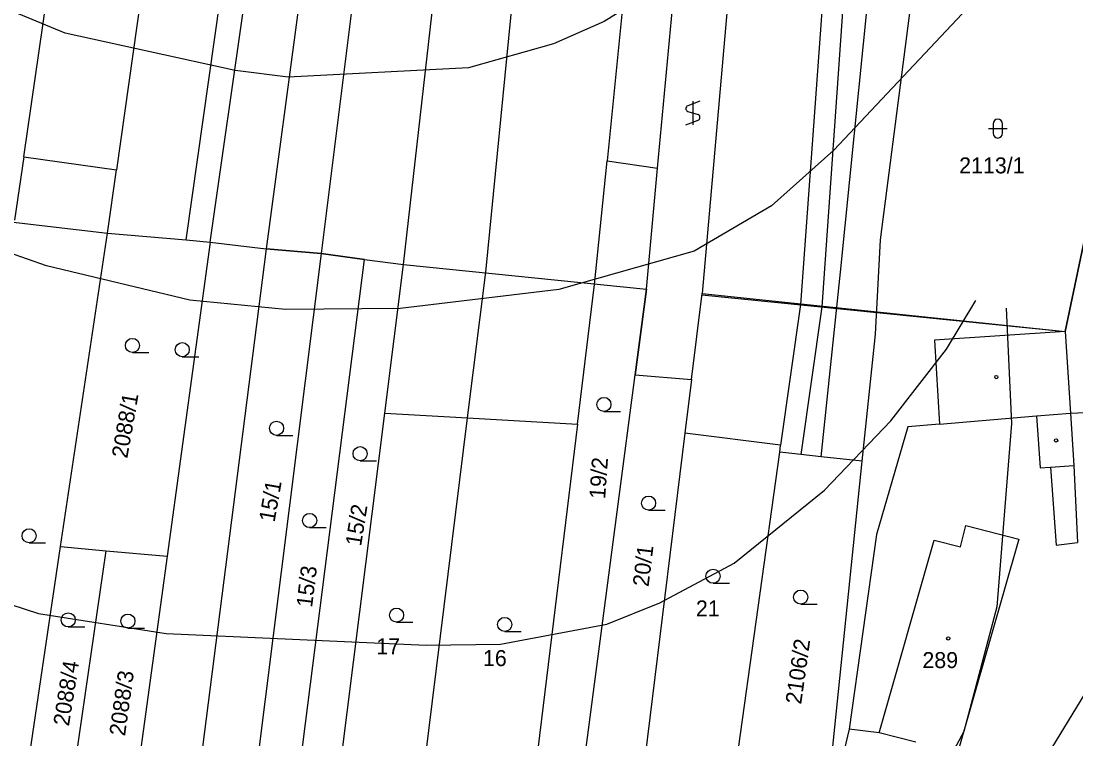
# Model space of a CAD drawing. Extents: x -555860 to -552701, y -1187050 to -1182291.
# Drawn here: x -554398.7 to -554286.6, y -1184314.5 to -1184238.2 of the extents above; entities that cross this region are included whole.
import ezdxf

# ---------------------------------------------------------------- set-up
doc = ezdxf.new("R2010")
doc.units = 0
for name, color, linetype in [('CYKLISTI_stav', 7, 'Continuous'), ('LEG_2b', 7, 'Continuous'), ('Level 25', 7, 'Continuous'), ('Level 32', 7, 'Continuous'), ('Level 40', 7, 'Continuous'), ('Level 41', 7, 'Continuous'), ('navrh_BV', 7, 'Continuous'), ('Poz předměty', 7, 'Continuous')]:
    doc.layers.add(name, color=color, linetype=linetype)

msp = doc.modelspace()

# ---------------------------------------------------------------- linework, layer by layer
at = {"layer": 'CYKLISTI_stav'}
for p, q in [((-554301.07, -1184281.07), (-554290.75, -1184280.2)), ((-554290.75, -1184280.2), (-554287.15, -1184279.89)), ((-554290.75, -1184280.2), (-554290.37, -1184285.71)), ((-554290.37, -1184285.71), (-554289.27, -1184285.64)), ((-554289.27, -1184285.64), (-554286.78, -1184285.47)), ((-554289.27, -1184285.64), (-554288.66, -1184293.92)), ((-554298.85, -1184294.11), (-554298.26, -1184291.84)), ((-554298.26, -1184291.84), (-554292.64, -1184293.31)), ((-554307.47, -1184313.88), (-554301.64, -1184293.39)), ((-554301.64, -1184293.39), (-554298.85, -1184294.11)), ((-554292.64, -1184293.31), (-554299.17, -1184316.05)), ((-554288.66, -1184293.92), (-554286.41, -1184293.66))]:
    msp.add_line(p, q, dxfattribs=at)
at = {"layer": 'Level 25'}
for p, q in [((-554326.54, -1184246.74), (-554327.84, -1184247.22)), ((-554327.29, -1184246.74), (-554327.29, -1184249.24)), ((-554327.84, -1184247.82), (-554326.74, -1184248.15)), ((-554328.04, -1184249.24), (-554326.74, -1184248.75)), ((-554295.38, -1184249.15), (-554295.38, -1184250.15)), ((-554294.38, -1184250.15), (-554294.38, -1184249.15)), ((-554295.88, -1184249.65), (-554293.88, -1184249.65)), ((-554386.88, -1184273.45), (-554385.13, -1184273.45)), ((-554381.58, -1184273.9), (-554379.83, -1184273.9)), ((-554336.75, -1184279.72), (-554335, -1184279.72)), ((-554371.56, -1184282.26), (-554369.81, -1184282.26)), ((-554362.67, -1184284.96), (-554360.92, -1184284.96)), ((-554332, -1184290.21), (-554330.25, -1184290.21)), ((-554368.04, -1184292.06), (-554366.29, -1184292.06)), ((-554397.86, -1184293.69), (-554396.11, -1184293.69)), ((-554325.15, -1184297.98), (-554323.4, -1184297.98)), ((-554315.83, -1184300.21), (-554314.08, -1184300.21)), ((-554393.7, -1184302.63), (-554391.95, -1184302.63)), ((-554387.36, -1184302.75), (-554385.61, -1184302.75)), ((-554358.8, -1184302.12), (-554357.05, -1184302.12)), ((-554347.3, -1184303.11), (-554345.55, -1184303.11))]:
    msp.add_line(p, q, dxfattribs=at)
for centre, radius in [((-554386.88, -1184272.7), 0.75), ((-554381.58, -1184273.15), 0.75), ((-554295.03, -1184276.07), 0.175), ((-554336.75, -1184278.97), 0.75), ((-554371.56, -1184281.51), 0.75), ((-554288.68, -1184282.79), 0.175), ((-554362.67, -1184284.21), 0.75), ((-554332, -1184289.46), 0.75), ((-554368.04, -1184291.31), 0.75), ((-554397.86, -1184292.94), 0.75), ((-554325.15, -1184297.23), 0.75), ((-554315.83, -1184299.46), 0.75), ((-554358.8, -1184301.37), 0.75), ((-554393.7, -1184301.88), 0.75), ((-554387.36, -1184302), 0.75), ((-554347.3, -1184302.36), 0.75), ((-554300.14, -1184303.85), 0.175)]:
    msp.add_circle(centre, radius, dxfattribs=at)
for centre, radius, start, end in [((-554327.71, -1184247.52), 0.329, 113.579, 246.421), ((-554326.87, -1184248.45), 0.329, 293.574, 66.426), ((-554294.88, -1184249.15), 0.5, 0, 180), ((-554294.88, -1184250.15), 0.5, 180, 359.9879)]:
    msp.add_arc(centre, radius, start, end, dxfattribs=at)
at = {"layer": 'Level 32'}
msp.add_lwpolyline([(-554434.03, -1184222.84), (-554435.88, -1184238.64), (-554430.45, -1184239.27), (-554428.47, -1184239.51), (-554423.54, -1184240.08), (-554425.5, -1184256.87), (-554417.69, -1184257.65), (-554415.69, -1184257.85), (-554410.7, -1184258.35), (-554408.36, -1184258.58), (-554389.53, -1184260.75), (-554381.18, -1184261.48), (-554378.6, -1184261.72), (-554372.66, -1184262.44), (-554366.82, -1184262.94), (-554362.22, -1184263.55), (-554358.07, -1184264.1), (-554332.24, -1184266.72), (-554333.44, -1184275.83), (-554327.43, -1184276.33), (-554326.32, -1184267.19), (-554287.72, -1184271.23), (-554283.44, -1184250.8)], dxfattribs=at)
at = {"layer": 'Level 40'}
msp.add_lwpolyline([(-554295.27, -1184233.79), (-554312.32, -1184251.94), (-554318.95, -1184257.87), (-554327.14, -1184262.67), (-554341.53, -1184266.76), (-554358.42, -1184268.76), (-554370.6, -1184268.87), (-554380.76, -1184267.89), (-554396, -1184264.22), (-554406.16, -1184260.69), (-554416.32, -1184256.32), (-554428.6, -1184250.11), (-554448.07, -1184238.39), (-554473.48, -1184221.04), (-554505.44, -1184195.21), (-554527.15, -1184180.46), (-554539.81, -1184170.02)], dxfattribs=at)
at = {"layer": 'Level 41'}
for points in [[(-554283.11, -1184174.19), (-554288.05, -1184179.27), (-554300.47, -1184200.43), (-554309.92, -1184214.54), (-554316.84, -1184222.87), (-554323.75, -1184229.5), (-554328.55, -1184233.17), (-554336.73, -1184238.25), (-554342.1, -1184240.65), (-554351.13, -1184243.19), (-554370.32, -1184244.18), (-554375.96, -1184243.47), (-554394.03, -1184239.52), (-554422.25, -1184227.81), (-554432.98, -1184222.45), (-554447.94, -1184213.84), (-554455.13, -1184209.04), (-554481.8, -1184187.73), (-554490.13, -1184182.09), (-554495.07, -1184179.69), (-554500.71, -1184178.14), (-554522.51, -1184174.82), (-554536.68, -1184170)], [(-554474.18, -1184237.55), (-554456.54, -1184262.95), (-554444.83, -1184275.37), (-554432.98, -1184284.11), (-554419.43, -1184292.3), (-554410.4, -1184296.82), (-554396.85, -1184301.19), (-554383.3, -1184303.31), (-554355.65, -1184304.58), (-554347.74, -1184304.44), (-554336.45, -1184302.32), (-554330.81, -1184300.06), (-554322.91, -1184295.83), (-554313.31, -1184288.07), (-554306.25, -1184280.73), (-554300.33, -1184273.11), (-554297.2, -1184267.91)], [(-554293.99, -1184268.72), (-554293.41, -1184281.01), (-554294.96, -1184300.48), (-554298.49, -1184313.75), (-554304, -1184324.05), (-554309.08, -1184329.84), (-554316.41, -1184335.34), (-554324.88, -1184337.6), (-554333.35, -1184337.46), (-554340.4, -1184336.47), (-554371.45, -1184329.84), (-554394.03, -1184326.87), (-554403.91, -1184324.48), (-554409.55, -1184322.22), (-554417.45, -1184316.85), (-554422.53, -1184311.49), (-554425.36, -1184307.54), (-554431.99, -1184295.83), (-554435.38, -1184291.45), (-554440.45, -1184286.51), (-554452.73, -1184276.92), (-554465.01, -1184266.05), (-554485.98, -1184245.54), (-554497.73, -1184248.25)], [(-554497.19, -1184301.56), (-554487.45, -1184301.9), (-554470.52, -1184300.89), (-554461.78, -1184299.99), (-554456.18, -1184297.53), (-554443.28, -1184304.72), (-554435.23, -1184312.9), (-554426.06, -1184324.33), (-554416.04, -1184332.09), (-554407.01, -1184336.89), (-554400.24, -1184339.43), (-554388.95, -1184342.54), (-554357.34, -1184345.64), (-554338.87, -1184346.66), (-554323.64, -1184345.31), (-554313.55, -1184341.05), (-554305.26, -1184335.45), (-554299.21, -1184330.08), (-554292.94, -1184321.78), (-554278.31, -1184297.8)]]:
    msp.add_lwpolyline(points, dxfattribs=at)
at = {"layer": 'navrh_BV'}
for p, q in [((-554311.59, -1184264.9), (-554303.25, -1184181.82)), ((-554307.33, -1184261.47), (-554297.21, -1184182.51)), ((-554382.95, -1184214.13), (-554388.58, -1184254.02)), ((-554381.18, -1184261.48), (-554374.61, -1184215.16)), ((-554378.6, -1184261.72), (-554372.03, -1184215.47)), ((-554366.48, -1184216.35), (-554372.66, -1184262.44)), ((-554361.09, -1184217.22), (-554366.82, -1184262.94)), ((-554358.07, -1184264.1), (-554352.81, -1184217.78)), ((-554349.32, -1184264.91), (-554344.76, -1184218.81)), ((-554333.08, -1184220.19), (-554336.42, -1184253.07)), ((-554331.04, -1184253.86), (-554327.99, -1184221.1)), ((-554322.27, -1184221.49), (-554326.32, -1184267.19)), ((-554312.54, -1184222.49), (-554315.85, -1184268.34)), ((-554310.35, -1184222.67), (-554313.59, -1184268.59)), ((-554398.44, -1184252.64), (-554395.27, -1184230.68)), ((-554283.44, -1184250.8), (-554287.72, -1184271.23)), ((-554398.44, -1184252.64), (-554399.41, -1184259.38)), ((-554398.44, -1184252.64), (-554388.58, -1184254.02)), ((-554337.76, -1184266.22), (-554336.42, -1184253.07)), ((-554336.42, -1184253.07), (-554331.04, -1184253.86)), ((-554389.53, -1184260.75), (-554388.58, -1184254.02)), ((-554332.24, -1184266.71), (-554331.04, -1184253.86)), ((-554394.52, -1184294.08), (-554389.53, -1184260.75)), ((-554389.53, -1184260.75), (-554381.18, -1184261.48)), ((-554381.18, -1184261.48), (-554378.6, -1184261.72)), ((-554307.89, -1184271.51), (-554307.33, -1184261.47)), ((-554378.6, -1184261.72), (-554383.19, -1184295.1)), ((-554372.66, -1184262.44), (-554379.92, -1184319.24)), ((-554366.82, -1184262.94), (-554372.66, -1184262.44)), ((-554366.82, -1184262.94), (-554373.95, -1184319.57)), ((-554369.37, -1184319.91), (-554362.22, -1184263.55)), ((-554362.22, -1184263.55), (-554366.82, -1184262.94)), ((-554362.22, -1184263.55), (-554358.07, -1184264.1)), ((-554360.06, -1184279.91), (-554358.07, -1184264.1)), ((-554351.24, -1184280.41), (-554349.32, -1184264.91)), ((-554313.64, -1184284.54), (-554311.59, -1184264.9)), ((-554339.57, -1184281.07), (-554337.76, -1184266.22)), ((-554333.44, -1184275.83), (-554332.24, -1184266.71)), ((-554327.43, -1184276.33), (-554326.32, -1184267.19)), ((-554315.85, -1184268.34), (-554317.96, -1184283.3)), ((-554313.59, -1184268.59), (-554315.82, -1184284.3)), ((-554308, -1184272.54), (-554307.89, -1184271.51)), ((-554287.72, -1184271.23), (-554301.62, -1184272.13)), ((-554287.72, -1184271.23), (-554287.15, -1184279.89)), ((-554309.29, -1184285.02), (-554308, -1184272.54)), ((-554301.62, -1184272.13), (-554301.07, -1184281.07)), ((-554339.52, -1184322.12), (-554333.44, -1184275.83)), ((-554333.44, -1184275.83), (-554327.43, -1184276.33)), ((-554327.43, -1184276.33), (-554328.13, -1184282.04)), ((-554365.13, -1184320.22), (-554360.06, -1184279.91)), ((-554360.06, -1184279.91), (-554351.24, -1184280.41)), ((-554356.23, -1184320.75), (-554351.24, -1184280.41)), ((-554351.24, -1184280.41), (-554339.57, -1184281.07)), ((-554287.15, -1184279.89), (-554279.13, -1184279.58)), ((-554287.15, -1184279.89), (-554286.78, -1184285.47)), ((-554339.57, -1184281.07), (-554344.52, -1184321.76)), ((-554304.45, -1184281.35), (-554307.77, -1184292.79)), ((-554301.07, -1184281.07), (-554304.45, -1184281.35)), ((-554328.13, -1184282.04), (-554332.41, -1184316.61)), ((-554317.96, -1184283.3), (-554328.13, -1184282.04)), ((-554318.06, -1184284.05), (-554317.96, -1184283.3)), ((-554322.7, -1184317.44), (-554318.06, -1184284.05)), ((-554315.82, -1184284.3), (-554318.06, -1184284.05)), ((-554313.64, -1184284.54), (-554315.82, -1184284.3)), ((-554309.29, -1184285.02), (-554313.64, -1184284.54)), ((-554313.32, -1184324.04), (-554309.29, -1184285.02)), ((-554286.78, -1184285.47), (-554286.41, -1184293.66)), ((-554307.77, -1184292.79), (-554310.68, -1184313.51)), ((-554398.04, -1184317.83), (-554394.52, -1184294.08)), ((-554394.52, -1184294.08), (-554389.66, -1184294.52)), ((-554392.86, -1184316.52), (-554389.66, -1184294.52)), ((-554389.66, -1184294.52), (-554383.19, -1184295.1)), ((-554383.19, -1184295.1), (-554386.21, -1184317.08)), ((-554310.68, -1184313.51), (-554311.55, -1184317.17)), ((-554307.47, -1184313.88), (-554310.68, -1184313.51)), ((-554303.6, -1184314.89), (-554307.47, -1184313.88))]:
    msp.add_line(p, q, dxfattribs=at)
at = {"layer": 'Poz předměty'}
for points in [[(-554408.36, -1184258.58), (-554389.53, -1184260.75)], [(-554378.6, -1184261.72), (-554372.66, -1184262.44)], [(-554358.07, -1184264.1), (-554332.24, -1184266.72)], [(-554326.33, -1184267.32), (-554287.72, -1184271.23)]]:
    msp.add_lwpolyline(points, dxfattribs=at)

# ---------------------------------------------------------------- texts
at = {"layer": 'LEG_2b'}
for s, p in [('2113/1', (-554298.98, -1184254.41)), ('21', (-554326.97, -1184301.51)), ('17', (-554360.95, -1184305.53)), ('16', (-554349.61, -1184306.79)), ('289', (-554302.89, -1184307))]:
    msp.add_text(s, height=1.7, dxfattribs=at).set_placement(p)
for s, rotation, p in [('2088/1', 80, (-554387.43, -1184284.77)), ('19/2', 86, (-554336.62, -1184289.07)), ('15/1', 80, (-554371.77, -1184291.56)), ('15/2', 81, (-554362.57, -1184294.11)), ('20/1', 83, (-554332.01, -1184298.41)), ('15/3', 83, (-554367.78, -1184300.62)), ('2106/2', 82, (-554315.78, -1184310.91)), ('2088/4', 81, (-554393.63, -1184313.23)), ('2088/3', 82, (-554387.67, -1184314.28))]:
    msp.add_text(s, height=1.7, rotation=rotation, dxfattribs=at).set_placement(p)

doc.saveas('drawing.dxf')
